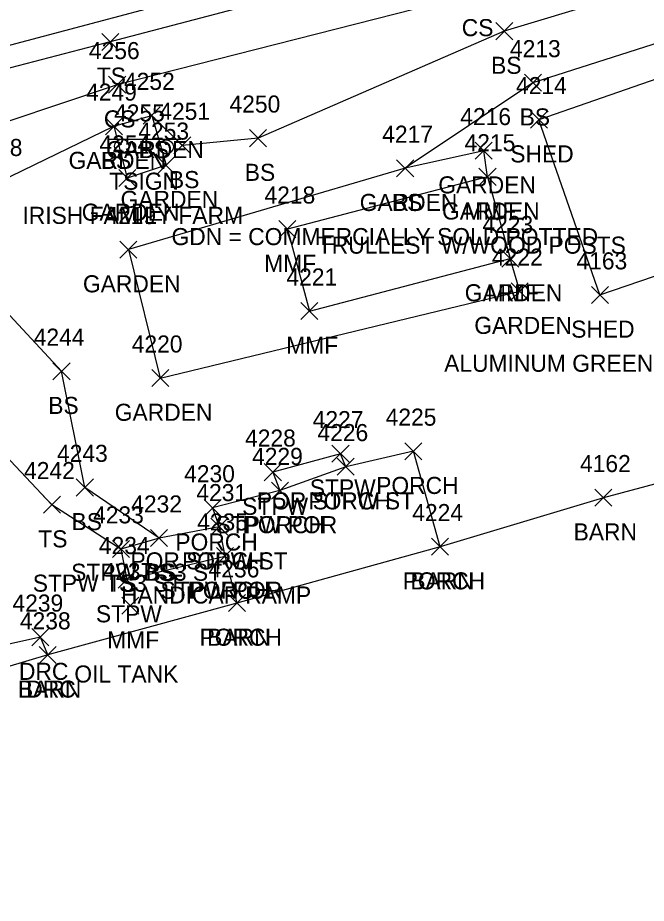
# Model space of a CAD drawing. Extents: x 1520648 to 1523413, y 732854 to 735518.
# Drawn here: x 1520895.7 to 1520969.4, y 733336.8 to 733440.6 of the extents above; entities that cross this region are included whole.
import ezdxf

# ---------------------------------------------------------------- set-up
doc = ezdxf.new("R2010")
doc.units = 0
for name, color, linetype in [('L_A', 7, 'Continuous'), ('L_C', 7, 'Continuous'), ('L_I', 7, 'Continuous'), ('L_TIC', 7, 'Continuous'), ('LAPB', 7, 'Continuous'), ('LBC', 7, 'Continuous'), ('LBF', 7, 'Continuous'), ('LDEFAULT', 7, 'Continuous'), ('LELB', 7, 'Continuous'), ('PSP', 7, 'Continuous'), ('R_A', 7, 'Continuous'), ('R_I', 7, 'Continuous'), ('R_TIC', 7, 'Continuous'), ('RDP', 7, 'Continuous'), ('S_A', 7, 'Continuous'), ('S_C', 7, 'Continuous'), ('S_I', 7, 'Continuous'), ('SSGN', 7, 'Continuous')]:
    doc.layers.add(name, color=color, linetype=linetype)

msp = doc.modelspace()

# ---------------------------------------------------------------- linework, layer by layer
at = {"layer": 'L_TIC'}
for points in [[(1520951.74, 733437.98), (1520953.74, 733439.98)], [(1520953.74, 733437.98), (1520951.74, 733439.98)], [(1520905.56, 733436.71), (1520907.56, 733438.71)], [(1520907.56, 733436.71), (1520905.56, 733438.71)], [(1520906.36, 733431.7), (1520908.36, 733433.7)], [(1520908.36, 733431.7), (1520906.36, 733433.7)], [(1520955.09, 733431.93), (1520957.09, 733433.93)], [(1520957.09, 733431.93), (1520955.09, 733433.93)], [(1520910.42, 733428.1), (1520912.42, 733430.1)], [(1520912.42, 733428.1), (1520910.42, 733430.1)], [(1520910.42, 733428.1), (1520912.42, 733430.1)], [(1520912.42, 733428.1), (1520910.42, 733430.1)], [(1520955.8, 733427.6), (1520957.8, 733429.6)], [(1520957.8, 733427.6), (1520955.8, 733429.6)], [(1520955.8, 733427.6), (1520957.8, 733429.6)], [(1520957.8, 733427.6), (1520955.8, 733429.6)], [(1520905.99, 733426.84), (1520907.99, 733428.84)], [(1520907.99, 733426.84), (1520905.99, 733428.84)], [(1520905.99, 733426.84), (1520907.99, 733428.84)], [(1520907.99, 733426.84), (1520905.99, 733428.84)], [(1520905.99, 733426.84), (1520907.99, 733428.84)], [(1520907.99, 733426.84), (1520905.99, 733428.84)], [(1520922.88, 733425.44), (1520924.88, 733427.44)], [(1520924.88, 733425.44), (1520922.88, 733427.44)], [(1520913.99, 733424.59), (1520915.99, 733426.59)], [(1520915.99, 733424.59), (1520913.99, 733426.59)], [(1520949.33, 733423.97), (1520951.33, 733425.97)], [(1520951.33, 733423.97), (1520949.33, 733425.97)], [(1520912.1, 733422.27), (1520914.1, 733424.27)], [(1520914.1, 733422.27), (1520912.1, 733424.27)], [(1520940.12, 733421.91), (1520942.12, 733423.91)], [(1520942.12, 733421.91), (1520940.12, 733423.91)], [(1520940.12, 733421.91), (1520942.12, 733423.91)], [(1520942.12, 733421.91), (1520940.12, 733423.91)], [(1520907.54, 733420.77), (1520909.54, 733422.77)], [(1520909.54, 733420.77), (1520907.54, 733422.77)], [(1520907.54, 733420.77), (1520909.54, 733422.77)], [(1520909.54, 733420.77), (1520907.54, 733422.77)], [(1520949.77, 733420.91), (1520951.77, 733422.91)], [(1520951.77, 733420.91), (1520949.77, 733422.91)], [(1520949.77, 733420.91), (1520951.77, 733422.91)], [(1520951.77, 733420.91), (1520949.77, 733422.91)], [(1520949.77, 733420.91), (1520951.77, 733422.91)], [(1520951.77, 733420.91), (1520949.77, 733422.91)], [(1520926.32, 733414.78), (1520928.32, 733416.78)], [(1520928.32, 733414.78), (1520926.32, 733416.78)], [(1520907.68, 733412.38), (1520909.68, 733414.38)], [(1520909.68, 733412.38), (1520907.68, 733414.38)], [(1520952.43, 733411.33), (1520954.43, 733413.33)], [(1520954.43, 733411.33), (1520952.43, 733413.33)], [(1520952.43, 733411.33), (1520954.43, 733413.33)], [(1520954.43, 733411.33), (1520952.43, 733413.33)], [(1520952.43, 733411.33), (1520954.43, 733413.33)], [(1520954.43, 733411.33), (1520952.43, 733413.33)], [(1520953.55, 733407.51), (1520955.55, 733409.51)], [(1520955.55, 733407.51), (1520953.55, 733409.51)], [(1520962.94, 733407.07), (1520964.94, 733409.07)], [(1520964.94, 733407.07), (1520962.94, 733409.07)], [(1520962.94, 733407.07), (1520964.94, 733409.07)], [(1520964.94, 733407.07), (1520962.94, 733409.07)], [(1520928.89, 733405.18), (1520930.89, 733407.18)], [(1520930.89, 733405.18), (1520928.89, 733407.18)], [(1520899.84, 733398.13), (1520901.84, 733400.13)], [(1520901.84, 733398.13), (1520899.84, 733400.13)], [(1520911.41, 733397.33), (1520913.41, 733399.33)], [(1520913.41, 733397.33), (1520911.41, 733399.33)], [(1520932.54, 733388.47), (1520934.54, 733390.47)], [(1520934.54, 733388.47), (1520932.54, 733390.47)], [(1520941.09, 733388.76), (1520943.09, 733390.76)], [(1520943.09, 733388.76), (1520941.09, 733390.76)], [(1520924.61, 733386.31), (1520926.61, 733388.31)], [(1520926.61, 733386.31), (1520924.61, 733388.31)], [(1520933.15, 733386.95), (1520935.15, 733388.95)], [(1520935.15, 733386.95), (1520933.15, 733388.95)], [(1520933.15, 733386.95), (1520935.15, 733388.95)], [(1520935.15, 733386.95), (1520933.15, 733388.95)], [(1520902.57, 733384.52), (1520904.57, 733386.52)], [(1520904.57, 733384.52), (1520902.57, 733386.52)], [(1520925.44, 733384.16), (1520927.44, 733386.16)], [(1520927.44, 733384.16), (1520925.44, 733386.16)], [(1520925.44, 733384.16), (1520927.44, 733386.16)], [(1520927.44, 733384.16), (1520925.44, 733386.16)], [(1520963.35, 733383.32), (1520965.35, 733385.32)], [(1520965.35, 733383.32), (1520963.35, 733385.32)], [(1520898.71, 733382.5), (1520900.71, 733384.5)], [(1520900.71, 733382.5), (1520898.71, 733384.5)], [(1520917.55, 733382.13), (1520919.55, 733384.13)], [(1520919.55, 733382.13), (1520917.55, 733384.13)], [(1520918.33, 733379.92), (1520920.33, 733381.92)], [(1520920.33, 733379.92), (1520918.33, 733381.92)], [(1520918.33, 733379.92), (1520920.33, 733381.92)], [(1520920.33, 733379.92), (1520918.33, 733381.92)], [(1520911.27, 733378.59), (1520913.27, 733380.59)], [(1520913.27, 733378.59), (1520911.27, 733380.59)], [(1520911.27, 733378.59), (1520913.27, 733380.59)], [(1520913.27, 733378.59), (1520911.27, 733380.59)], [(1520906.8, 733377.31), (1520908.8, 733379.31)], [(1520908.8, 733377.31), (1520906.8, 733379.31)], [(1520906.8, 733377.31), (1520908.8, 733379.31)], [(1520908.8, 733377.31), (1520906.8, 733379.31)], [(1520944.21, 733377.58), (1520946.21, 733379.58)], [(1520946.21, 733377.58), (1520944.21, 733379.58)], [(1520944.21, 733377.58), (1520946.21, 733379.58)], [(1520946.21, 733377.58), (1520944.21, 733379.58)], [(1520919, 733376.48), (1520921, 733378.48)], [(1520921, 733376.48), (1520919, 733378.48)], [(1520919, 733376.48), (1520921, 733378.48)], [(1520921, 733376.48), (1520919, 733378.48)], [(1520907.48, 733373.72), (1520909.48, 733375.72)], [(1520909.48, 733373.72), (1520907.48, 733375.72)], [(1520907.91, 733370.67), (1520909.91, 733372.67)], [(1520909.91, 733370.67), (1520907.91, 733372.67)], [(1520920.4, 733370.98), (1520922.4, 733372.98)], [(1520922.4, 733370.98), (1520920.4, 733372.98)], [(1520920.4, 733370.98), (1520922.4, 733372.98)], [(1520922.4, 733370.98), (1520920.4, 733372.98)], [(1520898.22, 733364.9), (1520900.22, 733366.9)], [(1520900.22, 733364.9), (1520898.22, 733366.9)]]:
    msp.add_lwpolyline(points, dxfattribs=at)
at = {"layer": 'LAPB'}
for points in [[(1520906.99, 733427.84), (1520911.42, 733429.1), (1520913.1, 733423.27), (1520908.54, 733421.77)], [(1520906.99, 733427.84), (1520908.54, 733421.77)], [(1520950.77, 733421.91), (1520950.33, 733424.97), (1520941.12, 733422.91), (1520908.68, 733413.38), (1520912.41, 733398.33), (1520954.55, 733408.51), (1520953.43, 733412.33)]]:
    msp.add_lwpolyline(points, dxfattribs=at)
at = {"layer": 'LBC'}
for points in [[(1520963.94, 733408.07), (1520992.53, 733417.84), (1520985.48, 733438.55), (1520956.8, 733428.6)], [(1520963.94, 733408.07), (1520956.8, 733428.6)], [(1521019.44, 733361.37), (1521009.83, 733396.39), (1521001.75, 733394.39), (1520996.44, 733392.85), (1520990.98, 733391.41), (1520976.46, 733387.53), (1520964.35, 733384.32), (1520945.21, 733378.58), (1520921.4, 733371.98), (1520899.22, 733365.9), (1520881.66, 733360.68)]]:
    msp.add_lwpolyline(points, dxfattribs=at)
at = {"layer": 'LBF'}
for points in [[(1520945.21, 733378.58), (1520942.09, 733389.76), (1520934.15, 733387.95), (1520926.44, 733385.16), (1520918.55, 733383.13), (1520919.33, 733380.92), (1520920, 733377.48), (1520921.4, 733371.98)], [(1520934.15, 733387.95), (1520933.54, 733389.47), (1520925.61, 733387.31), (1520926.44, 733385.16)], [(1520919.33, 733380.92), (1520912.27, 733379.59), (1520907.8, 733378.31), (1520908.48, 733374.72), (1520920, 733377.48)]]:
    msp.add_lwpolyline(points, dxfattribs=at)
at = {"layer": 'LDEFAULT'}
for points in [[(1520950.77, 733421.91), (1520927.32, 733415.78), (1520929.89, 733406.18), (1520953.43, 733412.33)], [(1520950.77, 733421.91), (1520953.43, 733412.33)]]:
    msp.add_lwpolyline(points, dxfattribs=at)
at = {"layer": 'LELB'}
for points in [[(1521084, 733484.54), (1521067.58, 733479.07), (1521049.77, 733473.83), (1520986.71, 733459.8), (1520946.37, 733448.2), (1520906.56, 733437.71), (1520887.62, 733432.82), (1520874.82, 733426.59), (1520851.23, 733419.6), (1520833.59, 733418.06), (1520824.1, 733415.79), (1520817.47, 733414.55), (1520789.23, 733404.3), (1520782.06, 733399.14), (1520771.54, 733396.06), (1520749.1, 733390.85), (1520744.37, 733386.94), (1520745.44, 733378.48), (1520749.8, 733369.39), (1520752.39, 733361.75), (1520762.08, 733336.81), (1520765.3, 733336.98)], [(1521080.83, 733474.71), (1521066.63, 733471.1), (1521052.37, 733467.65), (1521042.46, 733471.01), (1521038.84, 733468.84), (1521036.01, 733464.79), (1520988.24, 733449.66), (1520952.74, 733438.98), (1520923.88, 733426.44), (1520914.99, 733425.59), (1520911.42, 733429.1)], [(1521038.84, 733468.84), (1520987.4, 733455.86), (1520949.31, 733443.39), (1520907.36, 733432.7), (1520887.97, 733426.2), (1520871.27, 733419.86), (1520861.99, 733407.36), (1520847.71, 733403.77), (1520838.35, 733404.94), (1520822.18, 733406.09), (1520819.36, 733394.56), (1520817.03, 733387.06)], [(1521031.64, 733367.46), (1521024.5, 733394.1), (1521019.31, 733407.16), (1521009.23, 733420.85), (1521000.05, 733433.7), (1520990.68, 733444.03), (1520956.09, 733432.93), (1520941.12, 733422.91)], [(1520912.27, 733379.59), (1520903.57, 733385.52), (1520900.84, 733399.13), (1520889.71, 733411.1), (1520893.57, 733421.35), (1520906.99, 733427.84)], [(1520907.8, 733378.31), (1520899.71, 733383.5), (1520889.39, 733394.41)]]:
    msp.add_lwpolyline(points, dxfattribs=at)
at = {"layer": 'PSP'}
msp.add_lwpolyline([(1521366.85, 733559.74), (1521307.16, 733544.25), (1521244.3, 733528.24), (1521204.94, 733517.79), (1521152.82, 733504.37), (1521106.57, 733492.89), (1521080.1, 733485.88), (1521063.46, 733481.98), (1521018.86, 733470.55), (1520976.52, 733459.1), (1520931.66, 733447.13), (1520886.57, 733435.14), (1520877.93, 733432.71), (1520850.75, 733426.02), (1520817.82, 733417.13), (1520781.5, 733407.41), (1520747.69, 733397.94), (1520743.14, 733395.11), (1520720.82, 733389.47), (1520716.87, 733390.02), (1520705.4, 733386.95), (1520679.31, 733380.34)], dxfattribs=at)
at = {"layer": 'R_TIC'}
for points in [[(1520897.36, 733366.98), (1520899.36, 733368.98)], [(1520899.36, 733366.98), (1520897.36, 733368.98)], [(1520898.22, 733364.9), (1520900.22, 733366.9)], [(1520900.22, 733364.9), (1520898.22, 733366.9)]]:
    msp.add_lwpolyline(points, dxfattribs=at)
at = {"layer": 'RDP'}
msp.add_lwpolyline([(1520899.22, 733365.9), (1520898.36, 733367.98), (1520882.84, 733364.54), (1520881.66, 733360.68)], dxfattribs=at)
at = {"layer": 'SSGN'}
for p, q in [((1520906.24, 733426.32), (1520914.84, 733426.32)), ((1520910.26, 733425.42), (1520910.26, 733425.42))]:
    msp.add_line(p, q, dxfattribs=at)
for centre in [(1520907.9, 733425.49), (1520913.12, 733425.42)]:
    msp.add_circle(centre, 0.833, dxfattribs=at)

# ---------------------------------------------------------------- texts
at = {"layer": 'L_A'}
for s, p in [('CS', (1520947.75, 733438.39)), ('BS', (1520951.19, 733433.98)), ('TS', (1520904.97, 733432.71)), ('CS', (1520905.8, 733427.7)), ('BS', (1520954.53, 733427.93)), ('GARDEN', (1520906.08, 733424.1)), ('BS', (1520909.86, 733424.1)), ('SHED', (1520953.44, 733423.6)), ('SHED', (1520953.44, 733423.6)), ('GARDEN', (1520901.66, 733422.84)), ('GARDEN', (1520901.66, 733422.84)), ('BS', (1520905.43, 733422.84)), ('BS', (1520922.32, 733421.44)), ('BS', (1520913.43, 733420.59)), ('GARDEN', (1520945, 733419.97)), ('GARDEN', (1520907.76, 733418.27)), ('GARDEN', (1520935.79, 733417.91)), ('BS', (1520939.56, 733417.91)), ('GARDEN', (1520903.21, 733416.77)), ('GARDEN', (1520903.21, 733416.77)), ('GARDEN', (1520945.44, 733416.91)), ('MMF', (1520948.05, 733416.91)), ('MMF', (1520948.05, 733416.91)), ('MMF', (1520924.6, 733410.78)), ('GARDEN', (1520903.35, 733408.38)), ('GARDEN', (1520948.1, 733407.33)), ('MMF', (1520950.71, 733407.33)), ('MMF', (1520950.71, 733407.33)), ('GARDEN', (1520949.22, 733403.51)), ('SHED', (1520960.58, 733403.07)), ('SHED', (1520960.58, 733403.07)), ('MMF', (1520927.18, 733401.18)), ('BS', (1520899.28, 733394.13)), ('GARDEN', (1520907.08, 733393.33)), ('STPW', (1520929.94, 733384.47)), ('PORCH', (1520937.72, 733384.76)), ('POR STPW ST', (1520923.74, 733382.95)), ('PORCH', (1520929.78, 733382.95)), ('STPW', (1520922.01, 733382.31)), ('BS', (1520902.01, 733380.52)), ('STPW POR', (1520918.89, 733380.16)), ('PORCH', (1520922.06, 733380.16)), ('BARN', (1520960.86, 733379.32)), ('TS', (1520898.12, 733378.5)), ('PORCH', (1520914.18, 733378.13)), ('POR STPW ST', (1520908.92, 733375.92)), ('PORCH', (1520914.96, 733375.92)), ('STPW BS3 ST', (1520901.97, 733374.59)), ('BS', (1520910.71, 733374.59)), ('PORCH', (1520940.83, 733373.58)), ('BARN', (1520941.72, 733373.58)), ('STPW TS3 ST', (1520897.47, 733373.31)), ('TS', (1520906.21, 733373.31)), ('STPW POR', (1520912.44, 733372.48)), ('PORCH', (1520915.62, 733372.48)), ('STPW', (1520904.87, 733369.72)), ('MMF', (1520906.19, 733366.67)), ('PORCH', (1520917.02, 733366.98)), ('BARN', (1520917.91, 733366.98)), ('BARN', (1520895.73, 733360.9))]:
    msp.add_text(s, height=2, dxfattribs=at).set_placement(p)
at = {"layer": 'L_C'}
for s, p in [('GDN = COMMERCIALLY SOLD POTTED', (1520913.73, 733413.91)), ('TRULLEST W/WOOD POSTS', (1520930.88, 733412.91)), ('TRULLEST W/WOOD POSTS', (1520930.88, 733412.91)), ('ALUMINUM GREEN HOUSE', (1520945.69, 733399.07)), ('ALUMINUM GREEN HOUSE', (1520945.69, 733399.07)), ('HANDICAP RAMP', (1520907.81, 733371.92)), ('OIL TANK', (1520902.34, 733362.67))]:
    msp.add_text(s, height=2, dxfattribs=at).set_placement(p)
at = {"layer": 'L_I'}
for s, p in [('4213', (1520953.4, 733435.93)), ('4256', (1520904.05, 733435.7)), ('4252', (1520908.16, 733432.1)), ('4252', (1520908.16, 733432.1)), ('4214', (1520954.11, 733431.6)), ('4214', (1520954.11, 733431.6)), ('4249', (1520903.72, 733430.84)), ('4249', (1520903.72, 733430.84)), ('4249', (1520903.72, 733430.84)), ('4251', (1520912.3, 733428.59)), ('4250', (1520920.53, 733429.44)), ('4216', (1520947.58, 733427.97)), ('4253', (1520909.84, 733426.27)), ('4217', (1520938.43, 733425.91)), ('4217', (1520938.43, 733425.91)), ('4248', (1520890.31, 733424.35)), ('4254', (1520905.28, 733424.77)), ('4254', (1520905.28, 733424.77)), ('4215', (1520948.08, 733424.91)), ('4215', (1520948.08, 733424.91)), ('4215', (1520948.08, 733424.91)), ('4218', (1520924.63, 733418.78)), ('4219', (1520905.98, 733416.38)), ('4223', (1520950.17, 733415.33)), ('4223', (1520950.17, 733415.33)), ('4223', (1520950.17, 733415.33)), ('4222', (1520951.29, 733411.51)), ('4163', (1520961.2, 733411.07)), ('4163', (1520961.2, 733411.07)), ('4221', (1520927.2, 733409.18)), ('4244', (1520897.58, 733402.13)), ('4220', (1520909.07, 733401.33)), ('4227', (1520930.28, 733392.47)), ('4225', (1520938.83, 733392.76)), ('4228', (1520922.35, 733390.31)), ('4226', (1520930.84, 733390.95)), ('4226', (1520930.84, 733390.95)), ('4243', (1520900.31, 733388.52)), ('4229', (1520923.17, 733388.16)), ('4229', (1520923.17, 733388.16)), ('4162', (1520961.61, 733387.32)), ('4242', (1520896.45, 733386.5)), ('4230', (1520915.21, 733386.13)), ('4231', (1520916.64, 733383.92)), ('4231', (1520916.64, 733383.92)), ('4232', (1520909.01, 733382.59)), ('4232', (1520909.01, 733382.59)), ('4233', (1520904.54, 733381.31)), ('4233', (1520904.54, 733381.31)), ('4224', (1520941.95, 733381.58)), ('4224', (1520941.95, 733381.58)), ('4235', (1520916.74, 733380.48)), ('4235', (1520916.74, 733380.48)), ('4234', (1520905.22, 733377.72)), ('4237', (1520905.65, 733374.67)), ('4236', (1520918.08, 733374.98)), ('4236', (1520918.08, 733374.98)), ('4238', (1520895.96, 733368.9))]:
    msp.add_text(s, height=2, dxfattribs=at).set_placement(p)
at = {"layer": 'R_A'}
for p in [(1520895.85, 733362.98), (1520896.71, 733360.9)]:
    msp.add_text('DRC', height=2, dxfattribs=at).set_placement(p)
at = {"layer": 'R_I'}
for s, p in [('4239', (1520895.09, 733370.98)), ('4238', (1520895.96, 733368.9))]:
    msp.add_text(s, height=2, dxfattribs=at).set_placement(p)
at = {"layer": 'S_A'}
msp.add_text('TSIGN', height=2, dxfattribs=at).set_placement((1520906.44, 733420.4))
at = {"layer": 'S_C'}
msp.add_text('IRISH FAMILY FARM', height=2, dxfattribs=at).set_placement((1520896.26, 733416.4))
at = {"layer": 'S_I'}
msp.add_text('4255', height=2, dxfattribs=at).set_placement((1520907, 733428.4))

doc.saveas('drawing.dxf')
